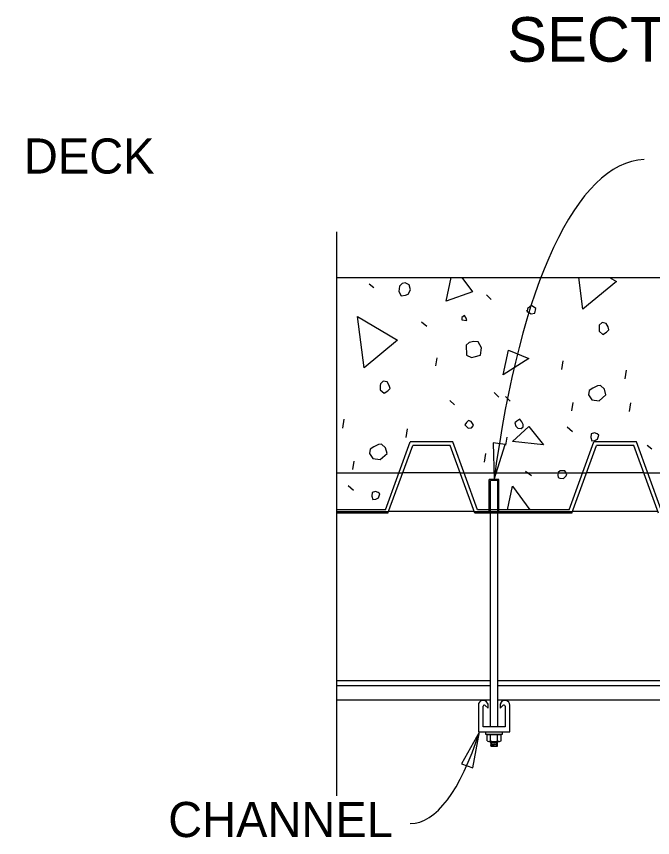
# Model space of a CAD drawing. Extents: x -1660015.2 to -1659984.9, y 2580594.2 to 2580616.7.
# Drawn here: x -1660002.937 to -1660000.2, y 2580601.644 to 2580605.179 of the extents above; entities that cross this region are included whole.
import ezdxf

# ---------------------------------------------------------------- set-up
doc = ezdxf.new("R2010")
doc.units = 0
for name, color, linetype in [('Default', 7, 'Continuous'), ('Miscellaneous', 7, 'Continuous'), ('Miscellaneous3', 7, 'Continuous'), ('PlotBorder_dp', 7, 'Continuous'), ('SheetLines_dp', 7, 'Continuous'), ('SteelGirder', 7, 'Continuous')]:
    doc.layers.add(name, color=color, linetype=linetype)

msp = doc.modelspace()

# ---------------------------------------------------------------- linework, layer by layer
at = {"layer": 'Default'}
for p, q in [((-1660001.5583, 2580603.2146), (-1660001.2748, 2580603.2146)), ((-1660001.0279, 2580603.2146), (-1660000.4844, 2580603.2146)), ((-1660000.2374, 2580603.2146), (-1659999.6939, 2580603.2146)), ((-1660001.5583, 2580603.0479), (-1660001.3355, 2580603.0479)), ((-1660000.9672, 2580603.0479), (-1660000.545, 2580603.0479)), ((-1660000.8974, 2580602.3186), (-1660001.5583, 2580602.3186)), ((-1660000.111, 2580602.3186), (-1660000.8662, 2580602.3186)), ((-1660000.8974, 2580602.2978), (-1660001.5583, 2580602.2978)), ((-1660000.0806, 2580602.2978), (-1660000.8662, 2580602.2978)), ((-1660000.8974, 2580602.2353), (-1660001.5583, 2580602.2353)), ((-1660000.9495, 2580602.2145), (-1660000.9495, 2580602.0999)), ((-1660000.9287, 2580602.1207), (-1660000.9287, 2580602.2097)), ((-1660000.9198, 2580602.2134), (-1660000.9079, 2580602.2015)), ((-1660000.9079, 2580602.2194), (-1660000.91, 2580602.2237)), ((-1660000.9079, 2580602.2015), (-1660000.9079, 2580602.2194)), ((-1659998.9494, 2580602.2353), (-1660000.8662, 2580602.2353)), ((-1660000.8535, 2580602.2237), (-1660000.8557, 2580602.2194)), ((-1660000.8557, 2580602.2194), (-1660000.8557, 2580602.2015)), ((-1660000.8557, 2580602.2015), (-1660000.8437, 2580602.2134)), ((-1660000.8349, 2580602.2097), (-1660000.8349, 2580602.1207)), ((-1660000.8141, 2580602.0999), (-1660000.8141, 2580602.2145)), ((-1660000.8349, 2580602.1207), (-1660000.9287, 2580602.1207)), ((-1660000.9495, 2580602.0999), (-1660000.8141, 2580602.0999))]:
    msp.add_line(p, q, dxfattribs=at)
for centre, radius, start, end in [((-1660000.9287, 2580602.2145), 0.0208, 26.1794, 179.9999), ((-1660000.9235, 2580602.2097), 0.0052, 45, 180), ((-1660000.8349, 2580602.2145), 0.0208, 0.0001, 153.8206), ((-1660000.8401, 2580602.2097), 0.0052, 360, 135)]:
    msp.add_arc(centre, radius, start, end, dxfattribs=at)
at = {"layer": 'Miscellaneous'}
for p, q in [((-1660001.4189, 2580604.0276), (-1660001.3992, 2580604.0122)), ((-1660000.9148, 2580603.9815), (-1660000.8938, 2580603.9613)), ((-1660001.1942, 2580603.8653), (-1660001.1708, 2580603.8456)), ((-1660001.1328, 2580603.6747), (-1660001.1267, 2580603.7099)), ((-1660000.5904, 2580603.6595), (-1660000.5849, 2580603.6972)), ((-1660000.318, 2580603.6186), (-1660000.3126, 2580603.6563)), ((-1660000.8822, 2580603.5606), (-1660000.8612, 2580603.5404)), ((-1660001.072, 2580603.5253), (-1660001.0517, 2580603.5074)), ((-1660000.8334, 2580603.5427), (-1660000.8124, 2580603.5224)), ((-1660000.548, 2580603.482), (-1660000.5419, 2580603.5172)), ((-1660000.2987, 2580603.4789), (-1660000.2932, 2580603.5166)), ((-1660001.5321, 2580603.4072), (-1660001.5267, 2580603.4449)), ((-1660000.568, 2580603.4119), (-1660000.5446, 2580603.3923)), ((-1660001.2598, 2580603.3663), (-1660001.2543, 2580603.404)), ((-1660001.3492, 2580603.0559), (-1660001.243, 2580603.3477)), ((-1660001.0597, 2580603.3477), (-1660001.243, 2580603.3477)), ((-1660000.9535, 2580603.0559), (-1660001.0597, 2580603.3477)), ((-1660000.8317, 2580603.3335), (-1660000.8256, 2580603.3687)), ((-1660000.5587, 2580603.0559), (-1660000.4526, 2580603.3477)), ((-1660000.2692, 2580603.3477), (-1660000.4526, 2580603.3477)), ((-1660000.1631, 2580603.0559), (-1660000.2692, 2580603.3477)), ((-1660001.3383, 2580603.0403), (-1660001.2321, 2580603.3321)), ((-1660001.0706, 2580603.3321), (-1660001.2321, 2580603.3321)), ((-1660000.9644, 2580603.0403), (-1660001.0706, 2580603.3321)), ((-1660000.5478, 2580603.0403), (-1660000.4416, 2580603.3321)), ((-1660000.2802, 2580603.3321), (-1660000.4416, 2580603.3321)), ((-1660000.174, 2580603.0403), (-1660000.2802, 2580603.3321)), ((-1660000.2234, 2580603.3334), (-1660000.2038, 2580603.318)), ((-1660000.9232, 2580603.2598), (-1660000.9178, 2580603.2974)), ((-1660001.4897, 2580603.2296), (-1660001.4837, 2580603.2649)), ((-1660000.7473, 2580603.2215), (-1660000.7215, 2580603.2025)), ((-1660001.5098, 2580603.1595), (-1660001.4864, 2580603.1399)), ((-1660001.3492, 2580603.0559), (-1660001.5583, 2580603.0559)), ((-1660000.5587, 2580603.0559), (-1660000.9535, 2580603.0559)), ((-1660001.3383, 2580603.0403), (-1660001.5583, 2580603.0403)), ((-1660000.5478, 2580603.0403), (-1660000.9644, 2580603.0403))]:
    msp.add_line(p, q, dxfattribs=at)
for points in [[(-1660001.0883, 2580603.9532), (-1660001.0665, 2580604.056)], [(-1660001.0208, 2580604.056), (-1660000.975, 2580603.9939), (-1660001.0883, 2580603.9532)], [(-1660000.4995, 2580603.9194), (-1660000.5169, 2580604.056)], [(-1660000.3854, 2580604.056), (-1660000.3554, 2580604.0383), (-1660000.4995, 2580603.9194)], [(-1660001.2895, 2580604.0183), (-1660001.291, 2580603.9946), (-1660001.281, 2580603.9766), (-1660001.2634, 2580603.9787), (-1660001.252, 2580603.9844), (-1660001.2414, 2580604.0027), (-1660001.2472, 2580604.0245), (-1660001.2649, 2580604.0327), (-1660001.277, 2580604.0294), (-1660001.2895, 2580604.0183)], [(-1660000.7401, 2580603.9093), (-1660000.7217, 2580603.8987), (-1660000.7072, 2580603.9026), (-1660000.7021, 2580603.9221), (-1660000.7211, 2580603.9351), (-1660000.7295, 2580603.9277), (-1660000.7385, 2580603.9227), (-1660000.7401, 2580603.9093), (-1660000.7414, 2580603.9141)], [(-1660001.4413, 2580603.6671), (-1660001.4693, 2580603.8873), (-1660001.2971, 2580603.7859), (-1660001.4413, 2580603.6671)], [(-1660001.0203, 2580603.873), (-1660000.999, 2580603.871), (-1660001.0016, 2580603.8806), (-1660001.0097, 2580603.8914), (-1660001.0204, 2580603.8833), (-1660001.0203, 2580603.873)], [(-1660000.4297, 2580603.8423), (-1660000.43, 2580603.8241), (-1660000.4134, 2580603.8105), (-1660000.3978, 2580603.8198), (-1660000.3877, 2580603.8303), (-1660000.3909, 2580603.8424), (-1660000.4002, 2580603.858), (-1660000.4167, 2580603.8614), (-1660000.4292, 2580603.8502), (-1660000.4297, 2580603.8423)], [(-1660001.0015, 2580603.7642), (-1660001.0001, 2580603.7206), (-1660000.9793, 2580603.7106), (-1660000.9673, 2580603.7138), (-1660000.9407, 2580603.721), (-1660000.9364, 2580603.7532), (-1660000.9507, 2580603.7778), (-1660000.9696, 2580603.7805), (-1660000.9889, 2580603.7753), (-1660001.0015, 2580603.7642)], [(-1660000.8428, 2580603.6359), (-1660000.8198, 2580603.743), (-1660000.7324, 2580603.7069), (-1660000.8428, 2580603.6359)], [(-1660001.3715, 2580603.59), (-1660001.3718, 2580603.5718), (-1660001.3552, 2580603.5581), (-1660001.3396, 2580603.5675), (-1660001.3294, 2580603.578), (-1660001.3327, 2580603.59), (-1660001.342, 2580603.6057), (-1660001.3585, 2580603.609), (-1660001.371, 2580603.5979), (-1660001.3715, 2580603.59)], [(-1660000.4757, 2580603.5505), (-1660000.462, 2580603.5283), (-1660000.4298, 2580603.524), (-1660000.4005, 2580603.5499), (-1660000.407, 2580603.5741), (-1660000.4242, 2580603.5902), (-1660000.437, 2580603.5893), (-1660000.4574, 2580603.5787), (-1660000.473, 2580603.5693), (-1660000.4757, 2580603.5505)], [(-1660000.7888, 2580603.4148), (-1660000.779, 2580603.4071), (-1660000.7656, 2580603.4055), (-1660000.7572, 2580603.4129), (-1660000.7574, 2580603.4233), (-1660000.763, 2580603.4347), (-1660000.7711, 2580603.4455), (-1660000.7843, 2580603.4367), (-1660000.7927, 2580603.4293), (-1660000.7888, 2580603.4148)], [(-1660001.0078, 2580603.4209), (-1660000.9936, 2580603.4065), (-1660000.9785, 2580603.408), (-1660000.9708, 2580603.4178), (-1660000.9721, 2580603.4227), (-1660000.9808, 2580603.4359), (-1660000.9924, 2580603.4405), (-1660001.0001, 2580603.4307), (-1660001.0078, 2580603.4209)], [(-1660000.8022, 2580603.3491), (-1660000.7318, 2580603.4146), (-1660000.6692, 2580603.3356), (-1660000.8022, 2580603.3491)], [(-1660000.4654, 2580603.3669), (-1660000.4615, 2580603.3524), (-1660000.4488, 2580603.3532), (-1660000.4373, 2580603.3589), (-1660000.4316, 2580603.376), (-1660000.4383, 2580603.3819), (-1660000.4499, 2580603.3866), (-1660000.4644, 2580603.3827), (-1660000.4654, 2580603.3669)], [(-1660001.4175, 2580603.2981), (-1660001.4038, 2580603.2759), (-1660001.3716, 2580603.2716), (-1660001.3423, 2580603.2976), (-1660001.3488, 2580603.3217), (-1660001.366, 2580603.3378), (-1660001.3787, 2580603.337), (-1660001.3992, 2580603.3263), (-1660001.4148, 2580603.317), (-1660001.4175, 2580603.2981)], [(-1660000.6056, 2580603.1948), (-1660000.5995, 2580603.1912), (-1660000.5837, 2580603.1903), (-1660000.5711, 2580603.2014), (-1660000.5682, 2580603.2099), (-1660000.577, 2580603.2231), (-1660000.5976, 2580603.2228), (-1660000.6059, 2580603.2154), (-1660000.6082, 2580603.2044), (-1660000.6056, 2580603.1948)], [(-1660001.4071, 2580603.1146), (-1660001.4033, 2580603.1001), (-1660001.3905, 2580603.1009), (-1660001.3791, 2580603.1065), (-1660001.3733, 2580603.1236), (-1660001.3801, 2580603.1296), (-1660001.3917, 2580603.1342), (-1660001.4062, 2580603.1304), (-1660001.4071, 2580603.1146)], [(-1660000.8242, 2580603.0559), (-1660000.8026, 2580603.1575), (-1660000.7277, 2580603.0559)]]:
    msp.add_lwpolyline(points, dxfattribs=at)
at = {"layer": 'Miscellaneous3'}
msp.add_line((-1660001.5583, 2580604.056), (-1659994.5491, 2580604.056), dxfattribs=at)
at = {"layer": 'SheetLines_dp'}
msp.add_lwpolyline([(-1660001.5583, 2580601.8245), (-1660001.5583, 2580604.252)], dxfattribs=at)
for points in [[(-1660000.8818, 2580603.1861), (-1660000.834, 2580603.3371), (-1660000.8864, 2580603.3444)], [(-1660000.9442, 2580602.0999), (-1660001.0225, 2580601.9622), (-1660000.9727, 2580601.9441)]]:
    msp.add_lwpolyline(points, close=True, dxfattribs=at)
for centre, major_axis, ratio, start_param, end_param in [((-1660000.0793, 2580601.6449), (0.1574, -2.9184), 0.2923, 3.141622, 4.140363), ((-1660001.2553, 2580603.3721), (-0.0129, 1.6676), 0.280094, 3.141615, 3.84244)]:
    msp.add_ellipse(centre, major_axis=major_axis, ratio=ratio, start_param=start_param, end_param=end_param, dxfattribs=at)
at = {"layer": 'SteelGirder'}
for p, q in [((-1660001.0279, 2580603.2146), (-1660001.2748, 2580603.2146)), ((-1660000.2374, 2580603.2146), (-1660000.4844, 2580603.2146)), ((-1660000.861, 2580603.1861), (-1660000.9026, 2580603.1861)), ((-1660000.9026, 2580603.0403), (-1660000.9026, 2580603.1861)), ((-1660000.8974, 2580602.1207), (-1660000.8974, 2580603.1809)), ((-1660000.8662, 2580603.1809), (-1660000.8974, 2580603.1809)), ((-1660000.8662, 2580602.1207), (-1660000.8662, 2580603.1809)), ((-1660000.861, 2580603.0403), (-1660000.861, 2580603.1861)), ((-1660000.9672, 2580603.0479), (-1660001.3355, 2580603.0479)), ((-1660000.1768, 2580603.0479), (-1660000.545, 2580603.0479)), ((-1660000.9119, 2580602.0604), (-1660000.9119, 2580602.0888)), ((-1660000.9119, 2580602.0888), (-1660000.8517, 2580602.0888)), ((-1660000.8968, 2580602.0604), (-1660000.8968, 2580602.0888)), ((-1660000.8667, 2580602.0604), (-1660000.8667, 2580602.0888)), ((-1660000.8517, 2580602.0604), (-1660000.8517, 2580602.0888)), ((-1660000.9043, 2580602.0582), (-1660000.8592, 2580602.0582)), ((-1660000.8975, 2580602.0576), (-1660000.8908, 2580602.0582)), ((-1660000.8975, 2580602.0576), (-1660000.8964, 2580602.0582)), ((-1660000.8922, 2580602.0554), (-1660000.8975, 2580602.0576)), ((-1660000.8975, 2580602.0524), (-1660000.8922, 2580602.0554)), ((-1660000.8975, 2580602.0524), (-1660000.8662, 2580602.0551)), ((-1660000.8922, 2580602.0502), (-1660000.8975, 2580602.0524)), ((-1660000.8975, 2580602.0472), (-1660000.8922, 2580602.0502)), ((-1660000.8975, 2580602.0472), (-1660000.8662, 2580602.0499)), ((-1660000.8922, 2580602.0451), (-1660000.8975, 2580602.0472)), ((-1660000.8975, 2580602.042), (-1660000.8922, 2580602.0451)), ((-1660000.8975, 2580602.042), (-1660000.8662, 2580602.0447)), ((-1660000.8922, 2580602.0398), (-1660000.8975, 2580602.042)), ((-1660000.8956, 2580602.0379), (-1660000.8922, 2580602.0398)), ((-1660000.8956, 2580602.0379), (-1660000.869, 2580602.0379)), ((-1660000.8855, 2580602.0379), (-1660000.8662, 2580602.0395)), ((-1660000.8715, 2580602.0572), (-1660000.8698, 2580602.0582)), ((-1660000.8662, 2580602.0551), (-1660000.8715, 2580602.0572)), ((-1660000.8715, 2580602.052), (-1660000.8662, 2580602.0551)), ((-1660000.8662, 2580602.0499), (-1660000.8715, 2580602.052)), ((-1660000.8715, 2580602.0469), (-1660000.8662, 2580602.0499)), ((-1660000.8662, 2580602.0447), (-1660000.8715, 2580602.0469)), ((-1660000.8715, 2580602.0417), (-1660000.8662, 2580602.0447)), ((-1660000.8662, 2580602.0395), (-1660000.8715, 2580602.0417)), ((-1660000.8691, 2580602.0379), (-1660000.8662, 2580602.0395))]:
    msp.add_line(p, q, dxfattribs=at)
msp.add_lwpolyline([(-1660000.8465, 2580602.0999), (-1660000.8465, 2580602.0888), (-1660000.9171, 2580602.0888), (-1660000.9171, 2580602.0999)], close=True, dxfattribs=at)
for centre, radius, start, end in [((-1660000.9043, 2580602.072), 0.0138, 236.9791, 303.0209), ((-1660000.8818, 2580602.11), 0.0519, 253.1396, 286.8604), ((-1660000.8592, 2580602.072), 0.0138, 236.9791, 303.0209)]:
    msp.add_arc(centre, radius, start, end, dxfattribs=at)

# ---------------------------------------------------------------- texts
at = {"layer": 'PlotBorder_dp'}
for s, height, p in [('SECTION A-A', 0.192, (-1660000.8255, 2580604.9845)), ('BRIDGE DECK', 0.1512, (-1660003.736, 2580604.5029)), ('CHANNEL', 0.1512, (-1660002.2838, 2580601.6465))]:
    msp.add_text(s, height=height, dxfattribs=at).set_placement(p)

doc.saveas('drawing.dxf')
